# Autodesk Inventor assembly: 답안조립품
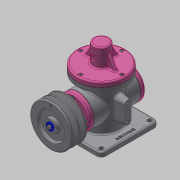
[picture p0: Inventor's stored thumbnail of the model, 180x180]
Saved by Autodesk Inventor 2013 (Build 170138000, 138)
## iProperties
Created: 2020-02
Part Number: 답안조립품
Document SubType Name: Assembly
Designer: Administrator
Mass: 1957.3 g
Surface Area: 2485.55 cm^2
Volume: 789.817 cm^3
Density: 2.47817 g/cm^3
Author: Administrator
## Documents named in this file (21)
- C:\Users\Administrator\Desktop\600206V1020\답안조립품.iam
- C:\Users\Administrator\Desktop\600206V1020\본체.ipt
- C:\Users\Administrator\Desktop\600206V1020\E-링.ipt
- C:\Users\Administrator\Desktop\600206V1020\V-벨트풀리.ipt
- C:\Users\Administrator\Desktop\600206V1020\가변스프링.ipt
- C:\Users\Administrator\Desktop\600206V1020\개스킷 A.ipt
- C:\Users\Administrator\Desktop\600206V1020\개스킷 B.ipt
- C:\Users\Administrator\Desktop\600206V1020\덮개.ipt
- C:\Users\Administrator\Desktop\600206V1020\뒤커버.ipt
- C:\Users\Administrator\Desktop\600206V1020\링크.ipt
- C:\Users\Administrator\Desktop\600206V1020\베어링 17 x 40 x 12.ipt
- C:\Users\Administrator\Desktop\600206V1020\볼트 M4 x 10.ipt
- C:\Users\Administrator\Desktop\600206V1020\슬라이더.ipt
- C:\Users\Administrator\Desktop\600206V1020\앞커버.ipt
- C:\Users\Administrator\Desktop\600206V1020\오일 실 17 30 8.ipt
- C:\Users\Administrator\Desktop\600206V1020\와셔 4x16.ipt
- C:\Users\Administrator\Desktop\600206V1020\육각 소켓 머리 볼트 M4 x 10.ipt
- C:\Users\Administrator\Desktop\600206V1020\클레비스 핀 6 x 22.ipt
- 클레비스 핀 6 x 22.ipt
- C:\Users\Administrator\Desktop\600206V1020\키 4 x 4 x 25.ipt
- C:\Users\Administrator\Desktop\600206V1020\편심축.ipt
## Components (6 placed, 5 different names)
1. E-링:1
2. V-벨트풀리:1
3. 가변스프링:1
4. 개스킷 A:1
5. 개스킷 B:1
6. 개스킷 A:2
